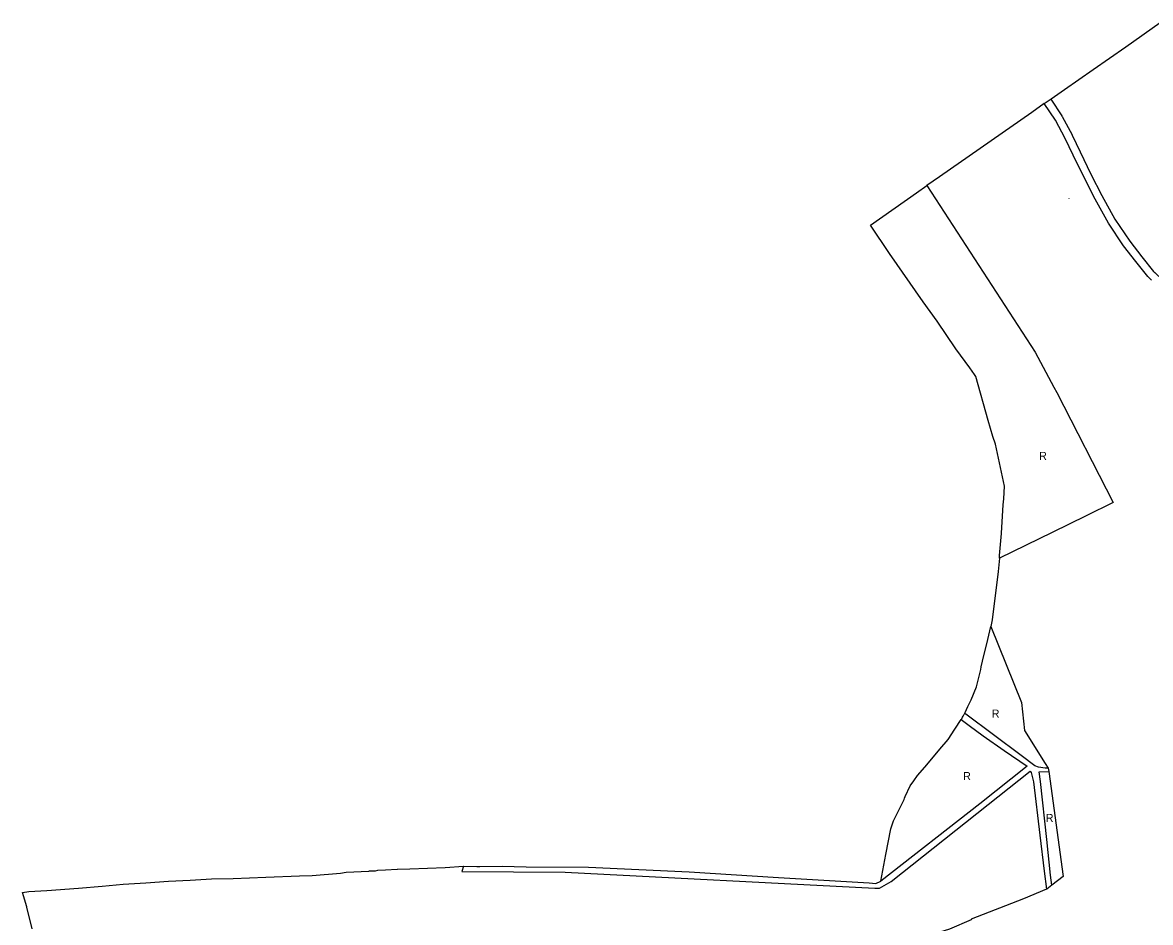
# Model space of a CAD drawing. Extents: x 7435758 to 7439981, y 5550649 to 5554049.
# Drawn here: x 7435884 to 7436617, y 5551708 to 5552293 of the extents above; entities that cross this region are included whole.
import ezdxf

# ---------------------------------------------------------------- set-up
doc = ezdxf.new("R2010")
doc.units = 0
for name, color, linetype in [('_Tereny dla których obowiązuje MPZP', 7, 'Continuous'), ('linie_rozgraniczające', 7, 'Continuous'), ('linie_zabudowy_nieprzekraczalne', 7, 'Continuous'), ('oznaczenia_przeznaczen', 7, 'Continuous')]:
    doc.layers.add(name, color=color, linetype=linetype)

msp = doc.modelspace()

# ---------------------------------------------------------------- linework, layer by layer
at = {"layer": '_Tereny dla których obowiązuje MPZP'}
for p, q in [((7436555.68, 5552229.34), (7436548.42, 5552240.17)), ((7436472.16, 5552186.9), (7436472.16, 5552186.9)), ((7436600.01, 5552147.75), (7436590.1, 5552162.54)), ((7436607.98, 5552137.55), (7436600.01, 5552147.75)), ((7436618.09, 5552125.56), (7436616.77, 5552126.8)), ((7436519.23, 5551944.76), (7436518.44, 5551936.13)), ((7436513.59, 5551900.47), (7436533.63, 5551851.18)), ((7436549.92, 5551729.75), (7436534.97, 5551723.42)), ((7436534.97, 5551723.42), (7436500.87, 5551710.27))]:
    msp.add_line(p, q, dxfattribs=at)
for points in [[(7436548.42, 5552240.17), (7436540.27, 5552234.38), (7436480.27, 5552192.63), (7436472.16, 5552186.9)], [(7436590.1, 5552162.54), (7436581.53, 5552178.18), (7436574.3, 5552192.11), (7436567.22, 5552206.72), (7436562.1, 5552217.46), (7436555.68, 5552229.34)], [(7436472.16, 5552186.9), (7436542.43, 5552078.58), (7436554.64, 5552056.01)], [(7436616.77, 5552126.8), (7436615.72, 5552127.77), (7436607.98, 5552137.55)], [(7436554.64, 5552056.01), (7436556.54, 5552052.5), (7436593.17, 5551981.05)], [(7436593.17, 5551981.05), (7436575.63, 5551972.43), (7436553.46, 5551961.56), (7436519.23, 5551944.76)], [(7436518.44, 5551936.13), (7436514.57, 5551904.75), (7436513.59, 5551900.47)], [(7436533.63, 5551851.18), (7436535.56, 5551832.98), (7436549, 5551811.54)], [(7436549, 5551811.54), (7436550.98, 5551808.46), (7436551.29, 5551806.18)], [(7436551.29, 5551806.18), (7436560.7, 5551737.97), (7436553.41, 5551732.38)], [(7436553.41, 5551732.38), (7436550.04, 5551729.8), (7436549.92, 5551729.75)], [(7436500.87, 5551710.27), (7436500.89, 5551709.81), (7436486.9, 5551703.76), (7436453.97, 5551693.56), (7436466.32, 5551673)]]:
    msp.add_lwpolyline(points, dxfattribs=at)
at = {"layer": 'linie_rozgraniczające'}
for p, q in [((7436601.5, 5552277.15), (7436623.75, 5552292.81)), ((7436580.15, 5552262.33), (7436601.5, 5552277.15)), ((7436561.67, 5552249.43), (7436580.15, 5552262.33)), ((7436548.42, 5552240.17), (7436552.97, 5552243.35)), ((7436552.97, 5552243.35), (7436561.67, 5552249.43)), ((7436555.68, 5552229.34), (7436548.42, 5552240.17)), ((7436555.68, 5552229.34), (7436552.05, 5552234.75)), ((7436562.1, 5552217.46), (7436555.68, 5552229.34)), ((7436567.22, 5552206.72), (7436562.1, 5552217.46)), ((7436574.3, 5552192.11), (7436567.22, 5552206.72)), ((7436581.53, 5552178.18), (7436574.3, 5552192.11)), ((7436472.16, 5552186.9), (7436472.16, 5552186.9)), ((7436435.45, 5552161.16), (7436465.42, 5552182.15)), ((7436590.1, 5552162.54), (7436581.53, 5552178.18)), ((7436600.01, 5552147.75), (7436590.1, 5552162.54)), ((7436600.01, 5552147.75), (7436590.1, 5552162.54)), ((7436447.75, 5552142.71), (7436435.45, 5552161.16)), ((7436607.98, 5552137.55), (7436600.01, 5552147.75)), ((7436607.98, 5552137.55), (7436600.01, 5552147.75)), ((7436469.63, 5552111.39), (7436447.75, 5552142.71)), ((7436615.72, 5552127.77), (7436607.98, 5552137.55)), ((7436616.77, 5552126.8), (7436615.72, 5552127.77)), ((7436618.09, 5552125.56), (7436616.77, 5552126.8)), ((7436618.09, 5552125.56), (7436616.77, 5552126.8)), ((7436478.72, 5552098.8), (7436469.63, 5552111.39)), ((7436490.95, 5552080.87), (7436478.72, 5552098.8)), ((7436500.13, 5552068.6), (7436490.95, 5552080.87)), ((7436503.04, 5552064.1), (7436500.13, 5552068.6)), ((7436503.85, 5552062.85), (7436503.04, 5552064.1)), ((7436511.98, 5552034.29), (7436503.85, 5552062.85)), ((7436514.97, 5552023.8), (7436511.98, 5552034.29)), ((7436516.77, 5552018.9), (7436514.97, 5552023.8)), ((7436522.51, 5551991.53), (7436516.77, 5552018.9)), ((7436522.03, 5551983.45), (7436522.51, 5551991.53)), ((7436520.72, 5551961.01), (7436521.81, 5551979.6)), ((7436521.81, 5551979.6), (7436522.03, 5551983.45)), ((7436519.39, 5551946.49), (7436520.7, 5551960.79)), ((7436520.7, 5551960.79), (7436520.72, 5551961.01)), ((7436519.23, 5551944.76), (7436519.39, 5551946.49)), ((7436519.23, 5551944.76), (7436519.23, 5551944.76)), ((7436519.23, 5551944.76), (7436519.23, 5551944.76)), ((7436519.23, 5551944.76), (7436519.23, 5551944.76)), ((7436511.63, 5551891.93), (7436513.59, 5551900.47)), ((7436513.59, 5551900.47), (7436513.59, 5551900.47)), ((7436513.59, 5551900.47), (7436513.59, 5551900.47)), ((7436513.59, 5551900.47), (7436513.59, 5551900.47)), ((7436513.59, 5551900.47), (7436533.63, 5551851.18)), ((7436508.36, 5551877.97), (7436511.63, 5551891.93)), ((7436507.51, 5551874.34), (7436508.36, 5551877.97)), ((7436504.29, 5551861.32), (7436507.17, 5551872.5)), ((7436507.17, 5551872.5), (7436507.51, 5551874.34)), ((7436500.88, 5551852.89), (7436504.29, 5551861.32)), ((7436497.05, 5551844.64), (7436498.81, 5551848.42)), ((7436498.81, 5551848.42), (7436500.88, 5551852.89)), ((7436490.32, 5551833.79), (7436494.49, 5551840.13)), ((7436494.49, 5551840.13), (7436494.78, 5551840.57)), ((7436494.49, 5551840.13), (7436499.66, 5551836.16)), ((7436494.78, 5551840.57), (7436495.3, 5551841.47)), ((7436495.3, 5551841.47), (7436495.75, 5551842.26)), ((7436495.75, 5551842.26), (7436496.42, 5551843.41)), ((7436496.42, 5551843.41), (7436496.71, 5551843.91)), ((7436496.71, 5551843.91), (7436496.73, 5551843.95)), ((7436497.33, 5551843.48), (7436496.71, 5551843.91)), ((7436496.73, 5551843.95), (7436497.05, 5551844.64)), ((7436533.45, 5551816.62), (7436497.33, 5551843.48)), ((7436485.87, 5551827.01), (7436490.32, 5551833.79)), ((7436499.66, 5551836.16), (7436508.73, 5551829.48)), ((7436480.63, 5551820.7), (7436485.87, 5551827.01)), ((7436508.73, 5551829.48), (7436522.41, 5551819.79)), ((7436475.39, 5551814.39), (7436480.63, 5551820.7)), ((7436522.41, 5551819.79), (7436537.39, 5551809.63)), ((7436470.74, 5551809.01), (7436475.39, 5551814.39)), ((7436542.25, 5551809.85), (7436533.45, 5551816.62)), ((7436448.94, 5551734.84), (7436539.29, 5551806.52)), ((7436463.66, 5551800.25), (7436466.09, 5551803.64)), ((7436466.09, 5551803.64), (7436470.74, 5551809.01)), ((7436537.39, 5551809.63), (7436506.61, 5551785.16)), ((7436539.29, 5551806.52), (7436539.81, 5551805.67)), ((7436539.81, 5551805.67), (7436541.35, 5551799.53)), ((7436544.72, 5551809.05), (7436542.25, 5551809.85)), ((7436549.1, 5551808.33), (7436544.72, 5551809.05)), ((7436545.01, 5551806.04), (7436551.29, 5551806.18)), ((7436545.98, 5551799.66), (7436545.01, 5551806.04)), ((7436550.98, 5551808.46), (7436549.1, 5551808.33)), ((7436457.9, 5551789.98), (7436461.22, 5551796.87)), ((7436461.22, 5551796.87), (7436463.66, 5551800.25)), ((7436541.35, 5551799.53), (7436545.49, 5551764.99)), ((7436550.12, 5551762.15), (7436545.98, 5551799.66)), ((7436457.28, 5551788.04), (7436457.59, 5551789.01)), ((7436457.59, 5551789.01), (7436457.9, 5551789.98)), ((7436506.61, 5551785.16), (7436442.28, 5551734.98)), ((7436450.42, 5551774.23), (7436457.28, 5551788.04)), ((7436448.63, 5551768.97), (7436450.42, 5551774.23)), ((7436445.44, 5551752.31), (7436448.63, 5551768.97)), ((7436545.49, 5551764.99), (7436548.46, 5551741.52)), ((7436552.42, 5551738.86), (7436550.12, 5551762.15)), ((7436442.28, 5551734.98), (7436445.44, 5551752.31)), ((7436159.04, 5551743.84), (7436171, 5551744.73)), ((7436171, 5551744.73), (7436169.95, 5551741.22)), ((7436171, 5551744.73), (7436179.6, 5551744.59)), ((7436179.6, 5551744.59), (7436181.46, 5551744.59)), ((7436181.46, 5551744.59), (7436196.17, 5551744.67)), ((7436196.17, 5551744.67), (7436211.63, 5551744.29)), ((7436021.2, 5551736.69), (7436042.47, 5551737.55)), ((7436042.47, 5551737.55), (7436064.31, 5551738.43)), ((7436064.31, 5551738.43), (7436072.6, 5551738.78)), ((7436072.6, 5551738.78), (7436091.05, 5551740.2)), ((7436091.05, 5551740.2), (7436094.63, 5551740.84)), ((7436094.63, 5551740.84), (7436109.31, 5551741.59)), ((7436109.31, 5551741.59), (7436109.85, 5551741.64)), ((7436109.85, 5551741.64), (7436110.7, 5551741.72)), ((7436110.7, 5551741.72), (7436113.71, 5551741.79)), ((7436113.71, 5551741.79), (7436115.16, 5551742.08)), ((7436115.16, 5551742.08), (7436120.21, 5551742.35)), ((7436120.21, 5551742.35), (7436127.76, 5551742.75)), ((7436127.76, 5551742.75), (7436128.08, 5551742.77)), ((7436128.08, 5551742.77), (7436136.04, 5551743.06)), ((7436136.04, 5551743.06), (7436159.04, 5551743.84)), ((7436169.95, 5551741.22), (7436236.93, 5551740.74)), ((7436211.63, 5551744.29), (7436252.22, 5551744.01)), ((7436236.93, 5551740.74), (7436438.25, 5551730.35)), ((7436252.22, 5551744.01), (7436317.65, 5551741.01)), ((7436317.65, 5551741.01), (7436375.57, 5551737.48)), ((7436375.57, 5551737.48), (7436434.62, 5551733.86)), ((7436548.46, 5551741.52), (7436549.92, 5551729.75)), ((7436553.41, 5551732.38), (7436552.42, 5551738.86)), ((7435900.04, 5551728.97), (7435920.75, 5551730.39)), ((7435920.75, 5551730.39), (7435936.03, 5551731.65)), ((7435936.03, 5551731.65), (7435949.83, 5551732.98)), ((7435949.83, 5551732.98), (7435964.39, 5551733.98)), ((7435964.39, 5551733.98), (7435979.14, 5551735.01)), ((7435979.14, 5551735.01), (7435993.33, 5551735.68)), ((7435993.33, 5551735.68), (7436007.09, 5551736.51)), ((7436007.09, 5551736.51), (7436021.2, 5551736.69)), ((7436434.62, 5551733.86), (7436439.02, 5551733.54)), ((7436438.25, 5551730.35), (7436441.23, 5551730.48)), ((7436439.02, 5551733.54), (7436442.28, 5551734.98)), ((7436441.23, 5551730.48), (7436448.94, 5551734.84)), ((7436549.92, 5551729.75), (7436534.97, 5551723.42)), ((7435884.33, 5551727.73), (7435888.36, 5551728.18)), ((7435887.16, 5551718.23), (7435884.33, 5551727.73)), ((7435888.36, 5551728.18), (7435900.04, 5551728.97)), ((7436534.97, 5551723.42), (7436500.87, 5551710.27)), ((7435887.2, 5551718.12), (7435887.16, 5551718.23)), ((7435890.47, 5551704), (7435887.2, 5551718.12))]:
    msp.add_line(p, q, dxfattribs=at)
for points in [[(7436590.1, 5552162.54), (7436581.53, 5552178.18), (7436574.3, 5552192.11), (7436567.22, 5552206.72), (7436562.1, 5552217.46), (7436555.68, 5552229.34)], [(7436465.42, 5552182.15), (7436472.16, 5552186.9)], [(7436472.16, 5552186.9), (7436542.43, 5552078.58), (7436554.64, 5552056.01)], [(7436616.77, 5552126.8), (7436615.72, 5552127.77), (7436607.98, 5552137.55)], [(7436554.64, 5552056.01), (7436556.54, 5552052.5), (7436593.17, 5551981.05)], [(7436593.17, 5551981.05), (7436575.63, 5551972.43), (7436553.46, 5551961.56), (7436519.23, 5551944.76)], [(7436533.63, 5551851.18), (7436535.56, 5551832.98), (7436549, 5551811.54)], [(7436549, 5551811.54), (7436550.98, 5551808.46), (7436551.29, 5551806.18)], [(7436551.29, 5551806.18), (7436560.7, 5551737.97), (7436553.41, 5551732.38)], [(7436553.41, 5551732.38), (7436550.04, 5551729.8), (7436549.92, 5551729.75)], [(7436500.87, 5551710.27), (7436500.89, 5551709.81), (7436486.9, 5551703.76), (7436453.97, 5551693.56), (7436466.32, 5551673)]]:
    msp.add_lwpolyline(points, dxfattribs=at)
at = {"layer": 'linie_zabudowy_nieprzekraczalne'}
msp.add_line((7436564.34, 5552178.53), (7436564.41, 5552178.4), dxfattribs=at)
msp.add_lwpolyline([(7436552.58, 5552242.96), (7436559.84, 5552232.12), (7436559.91, 5552232.01), (7436560.08, 5552231.73), (7436560.08, 5552231.72), (7436566.5, 5552219.83), (7436566.62, 5552219.61), (7436571.73, 5552208.89), (7436578.78, 5552194.36), (7436585.94, 5552180.53), (7436594.39, 5552165.14), (7436604.07, 5552150.69), (7436611.91, 5552140.64), (7436619.4, 5552131.18), (7436620.16, 5552130.48), (7436620.19, 5552130.45), (7436625.76, 5552125.22)], dxfattribs=at)

# ---------------------------------------------------------------- texts
at = {"layer": 'oznaczenia_przeznaczen'}
for p in [(7436545.04, 5552008.69), (7436514.26, 5551841.29), (7436495.67, 5551800.68), (7436549.4, 5551773.46)]:
    msp.add_text('R', height=5.2, dxfattribs=at).set_placement(p)

doc.saveas('drawing.dxf')
